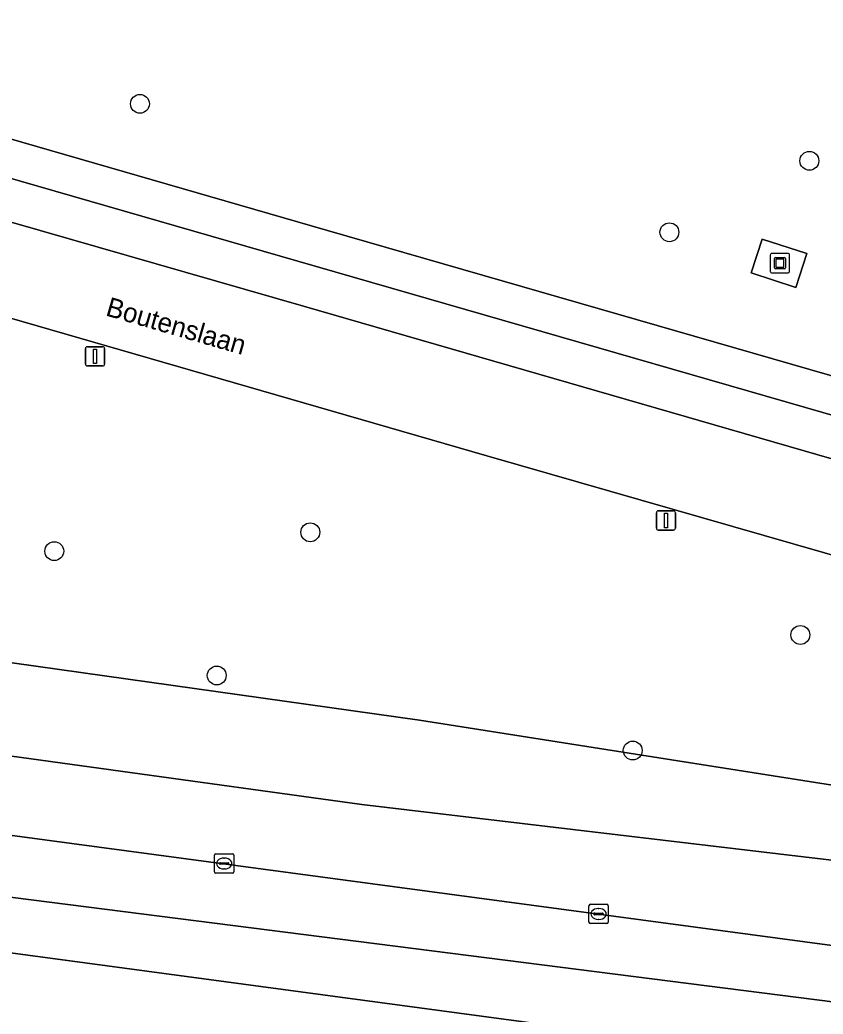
# Model space of a CAD drawing. Extents: x 161402 to 161933, y 381647 to 382315.
# Drawn here: x 161443.8 to 161485.4, y 381705.2 to 381756.7 of the extents above; entities that cross this region are included whole.
import ezdxf

# ---------------------------------------------------------------- set-up
doc = ezdxf.new("R2010")
doc.units = 0
for name, color, linetype in [('IMGEO_Berm_groen', 7, 'Continuous'), ('IMGEO_Boom', 7, 'Continuous'), ('IMGEO_Groenvoorziening', 7, 'Continuous'), ('IMGEO_Kolk', 7, 'Continuous'), ('IMGEO_Kunstobject', 7, 'Continuous'), ('IMGEO_Lichtmast', 7, 'Continuous'), ('IMGEO_Openbare_ruimte_label', 7, 'Continuous'), ('IMGEO_Parkeervlak_halfverhard', 7, 'Continuous'), ('IMGEO_Rijbaan_lokaal_open', 7, 'Continuous'), ('IMGEO_Rijbaan_regionaal_gesloten', 7, 'Continuous'), ('IMGEO_Voetpad_open', 7, 'Continuous')]:
    doc.layers.add(name, color=color, linetype=linetype)

msp = doc.modelspace()

# ---------------------------------------------------------------- linework, layer by layer
at = {"layer": 'IMGEO_Berm_groen'}
for points in [[(161550.274, 381710.457), (161521.825, 381718.639), (161511.545, 381721.598), (161506.198, 381723.137), (161493.45, 381726.806), (161492.294, 381723.245), (161489.647, 381724.03), (161487.722, 381724.601), (161488.157, 381726.039), (161486.53, 381726.524), (161487.109, 381728.631), (161467.984, 381734.136), (161424.232, 381746.77), (161422.307, 381747.284), (161421.908, 381747.401), (161419.883, 381747.931), (161419.264, 381745.56), (161418.377, 381745.755)], [(161412.782, 381706.187), (161412.983, 381707.708), (161413.616, 381712.377), (161413.962, 381714.993), (161414.406, 381718.345), (161414.713, 381720.679), (161414.729, 381720.986), (161414.872, 381722.243), (161415.659, 381723.737), (161416.807, 381724.974), (161417.694, 381725.496), (161419.991, 381725.975), (161422.336, 381726.035), (161425.949, 381725.851), (161464.494, 381720.439), (161486.232, 381717.019)], [(161486.232, 381717.019), (161464.494, 381720.439), (161425.949, 381725.851), (161422.336, 381726.035), (161419.991, 381725.975), (161417.694, 381725.496), (161416.807, 381724.974), (161415.659, 381723.737), (161414.872, 381722.243), (161414.729, 381720.986), (161421.115, 381720.1), (161421.193, 381720.541), (161421.637, 381721.268), (161422.47, 381721.45), (161461.503, 381716.064), (161500, 381711.507)], [(161619.348, 381684.737), (161582.68, 381689.648), (161413.616, 381712.377), (161412.983, 381707.708), (161436.501, 381704.561), (161496.223, 381696.587), (161500, 381696.081), (161535.035, 381691.391), (161618.812, 381680.164), (161638.545, 381677.519), (161680.265, 381671.952)]]:
    msp.add_lwpolyline(points, dxfattribs=at)
msp.add_lwpolyline([(161506.756, 381710.29), (161500, 381711.507), (161461.503, 381716.064), (161422.47, 381721.45), (161421.637, 381721.268), (161421.193, 381720.541), (161421.115, 381720.1), (161414.729, 381720.986), (161414.713, 381720.679), (161414.406, 381718.345), (161620.052, 381690.763), (161588.605, 381697.419), (161577.445, 381699.644), (161568.717, 381701.384), (161533, 381706.394)], close=True, dxfattribs=at)
at = {"layer": 'IMGEO_Boom'}
for centre in [(161450.011, 381752.364), (161484.7, 381749.414), (161477.448, 381745.711), (161458.839, 381730.166), (161445.572, 381729.191), (161484.233, 381724.847), (161453.99, 381722.748), (161475.546, 381718.86)]:
    msp.add_circle(centre, 0.489, dxfattribs=at)
at = {"layer": 'IMGEO_Groenvoorziening'}
msp.add_lwpolyline([(161421.928, 381756.713), (161459.737, 381745.805), (161494.788, 381735.694), (161509.376, 381731.463), (161508.478, 381735.358), (161508.026, 381737.392), (161507.691, 381738.967), (161506.96, 381742.59), (161506.607, 381744.402), (161506.258, 381746.213), (161505.559, 381749.824), (161505.195, 381751.629), (161504.692, 381753.976)], dxfattribs=at)
msp.add_lwpolyline([(161484.569, 381744.613), (161484.001, 381742.857), (161481.687, 381743.605), (161482.255, 381745.361)], close=True, dxfattribs=at)
at = {"layer": 'IMGEO_Kolk'}
for p, q in [((161453.875, 381712.582), (161453.875, 381713.434)), ((161453.95, 381713.508), (161454.802, 381713.508)), ((161454.363, 381713.288), (161454.388, 381713.288)), ((161454.876, 381713.434), (161454.876, 381712.582)), ((161454.134, 381713.002), (161454.134, 381713.014)), ((161454.572, 381712.965), (161454.174, 381712.965)), ((161454.177, 381713.051), (161454.575, 381713.051)), ((161454.386, 381712.728), (161454.361, 381712.728)), ((161454.618, 381713.014), (161454.618, 381713.002)), ((161454.802, 381712.508), (161453.95, 381712.508)), ((161473.276, 381709.967), (161473.276, 381710.819)), ((161473.351, 381710.893), (161474.203, 381710.893)), ((161473.764, 381710.673), (161473.789, 381710.673)), ((161474.277, 381710.819), (161474.277, 381709.967)), ((161473.535, 381710.387), (161473.535, 381710.399)), ((161473.973, 381710.35), (161473.575, 381710.35)), ((161473.578, 381710.436), (161473.976, 381710.436)), ((161473.787, 381710.113), (161473.762, 381710.113)), ((161474.019, 381710.399), (161474.019, 381710.387)), ((161474.203, 381709.893), (161473.351, 381709.893))]:
    msp.add_line(p, q, dxfattribs=at)
for points in [[(161453.875, 381712.582), (161453.875, 381713.434)], [(161453.95, 381713.508), (161454.802, 381713.508)], [(161454.876, 381713.434), (161454.876, 381712.582)], [(161454.802, 381712.508), (161453.95, 381712.508)], [(161473.276, 381709.967), (161473.276, 381710.819)], [(161473.351, 381710.893), (161474.203, 381710.893)], [(161474.277, 381710.819), (161474.277, 381709.967)], [(161474.203, 381709.893), (161473.351, 381709.893)]]:
    msp.add_lwpolyline(points, dxfattribs=at)
for centre, radius, start, end in [((161453.952, 381713.432), 0.0765, 91.552, 178.448), ((161453.952, 381713.432), 0.0765, 91.552, 178.448), ((161454.8, 381713.432), 0.0765, 1.552, 88.448), ((161454.8, 381713.432), 0.0765, 1.552, 88.448), ((161453.952, 381712.584), 0.0765, 181.552, 268.448), ((161453.952, 381712.584), 0.0765, 181.552, 268.448), ((161454.174, 381713.011), 0.0403, 85.8775, 175.7526), ((161454.171, 381713.001), 0.0366, 178.938, 274.7102), ((161454.575, 381713.008), 0.043, 264.8664, 352.4533), ((161454.579, 381713.013), 0.0386, 1.7309, 96.639), ((161454.8, 381712.584), 0.0765, 271.552, 358.448), ((161454.8, 381712.584), 0.0765, 271.552, 358.448), ((161473.353, 381710.817), 0.0765, 91.552, 178.448), ((161473.353, 381710.817), 0.0765, 91.552, 178.448), ((161474.201, 381710.817), 0.0765, 1.552, 88.448), ((161474.201, 381710.817), 0.0765, 1.552, 88.448), ((161473.575, 381710.396), 0.0403, 85.8775, 175.7526), ((161473.572, 381710.386), 0.0366, 178.938, 274.7102), ((161473.976, 381710.393), 0.043, 264.8664, 352.4533), ((161473.98, 381710.398), 0.0386, 1.7309, 96.639), ((161473.353, 381709.969), 0.0765, 181.552, 268.448), ((161473.353, 381709.969), 0.0765, 181.552, 268.448), ((161474.201, 381709.969), 0.0765, 271.552, 358.448), ((161474.201, 381709.969), 0.0765, 271.552, 358.448)]:
    msp.add_arc(centre, radius, start, end, dxfattribs=at)
for centre, major_axis, ratio, start_param, end_param in [((161454.362, 381713.008), (-0.387, 0.002), 0.722429, 4.712389, 7.853982), ((161454.387, 381713.008), (-0.39, 0.002), 0.717154, 1.570796, 4.712389), ((161473.763, 381710.393), (-0.387, 0.002), 0.722429, 4.712389, 7.853982), ((161473.788, 381710.393), (-0.39, 0.002), 0.717154, 1.570796, 4.712389)]:
    msp.add_ellipse(centre, major_axis=major_axis, ratio=ratio, start_param=start_param, end_param=end_param, dxfattribs=at)
at = {"layer": 'IMGEO_Kunstobject'}
for p, q in [((161482.677, 381744.526), (161482.677, 381743.685)), ((161482.677, 381744.526), (161482.677, 381743.685)), ((161483.593, 381744.61), (161482.752, 381744.61)), ((161483.593, 381744.61), (161482.752, 381744.61)), ((161483.677, 381743.694), (161483.677, 381744.535)), ((161483.677, 381743.694), (161483.677, 381744.535)), ((161482.891, 381743.874), (161482.891, 381744.348)), ((161482.941, 381744.398), (161483.415, 381744.398)), ((161482.971, 381744.298), (161482.971, 381743.924)), ((161483.365, 381744.318), (161482.991, 381744.318)), ((161483.385, 381743.924), (161483.385, 381744.298)), ((161483.465, 381744.348), (161483.465, 381743.874)), ((161482.761, 381743.61), (161483.602, 381743.61)), ((161482.761, 381743.61), (161483.602, 381743.61)), ((161483.415, 381743.824), (161482.941, 381743.824)), ((161482.991, 381743.904), (161483.365, 381743.904))]:
    msp.add_line(p, q, dxfattribs=at)
for centre, radius, start, end in [((161482.755, 381744.532), 0.0779, 92.4484, 184.2845), ((161482.755, 381744.532), 0.0779, 92.4484, 184.2845), ((161483.599, 381744.532), 0.0779, 2.4484, 94.2845), ((161483.599, 381744.532), 0.0779, 2.4484, 94.2845), ((161482.941, 381744.348), 0.05, 90, 180), ((161482.991, 381744.298), 0.02, 90, 180), ((161483.365, 381744.298), 0.02, 360, 90), ((161483.415, 381744.348), 0.05, 360, 90), ((161482.755, 381743.688), 0.0779, 182.4484, 274.2845), ((161482.755, 381743.688), 0.0779, 182.4484, 274.2845), ((161482.941, 381743.874), 0.05, 180, 270), ((161482.991, 381743.924), 0.02, 180, 270), ((161483.365, 381743.924), 0.02, 270, 0), ((161483.415, 381743.874), 0.05, 270, 0), ((161483.599, 381743.688), 0.0779, 272.4484, 4.2845), ((161483.599, 381743.688), 0.0779, 272.4484, 4.2845)]:
    msp.add_arc(centre, radius, start, end, dxfattribs=at)
at = {"layer": 'IMGEO_Lichtmast'}
for p, q in [((161447.187, 381738.883), (161447.187, 381739.683)), ((161447.187, 381739.683), (161447.187, 381738.883)), ((161447.287, 381739.783), (161448.077, 381739.783)), ((161448.077, 381739.783), (161447.287, 381739.783)), ((161448.177, 381739.683), (161448.177, 381738.883)), ((161448.177, 381738.883), (161448.177, 381739.683)), ((161448.077, 381738.783), (161447.287, 381738.783)), ((161447.287, 381738.783), (161448.077, 381738.783)), ((161476.77, 381730.378), (161476.77, 381731.178)), ((161476.77, 381731.178), (161476.77, 381730.378)), ((161476.87, 381731.278), (161477.66, 381731.278)), ((161477.66, 381731.278), (161476.87, 381731.278)), ((161477.76, 381731.178), (161477.76, 381730.378)), ((161477.76, 381730.378), (161477.76, 381731.178)), ((161477.66, 381730.278), (161476.87, 381730.278)), ((161476.87, 381730.278), (161477.66, 381730.278))]:
    msp.add_line(p, q, dxfattribs=at)
for points in [[(161447.607, 381739.658), (161447.757, 381739.658), (161447.757, 381738.908), (161447.607, 381738.908), (161447.607, 381739.658)], [(161477.19, 381731.153), (161477.34, 381731.153), (161477.34, 381730.403), (161477.19, 381730.403), (161477.19, 381731.153)]]:
    msp.add_lwpolyline(points, dxfattribs=at)
for centre, start, end in [((161447.287, 381739.683), 90, 180), ((161447.287, 381739.683), 90, 180), ((161448.077, 381739.683), 0, 90), ((161448.077, 381739.683), 360, 90), ((161447.287, 381738.883), 180, 270), ((161447.287, 381738.883), 180, 270), ((161448.077, 381738.883), 270, 0), ((161448.077, 381738.883), 270, 0), ((161476.87, 381731.178), 90, 180), ((161476.87, 381731.178), 90, 180), ((161477.66, 381731.178), 0, 90), ((161477.66, 381731.178), 360, 90), ((161476.87, 381730.378), 180, 270), ((161476.87, 381730.378), 180, 270), ((161477.66, 381730.378), 270, 0), ((161477.66, 381730.378), 270, 0)]:
    msp.add_arc(centre, 0.1, start, end, dxfattribs=at)
at = {"layer": 'IMGEO_Parkeervlak_halfverhard'}
msp.add_lwpolyline([(161423.537, 381751.922), (161458.483, 381741.876), (161493.525, 381731.759), (161507.502, 381727.744), (161512.889, 381726.196), (161550.839, 381715.295), (161551.402, 381717.349), (161494.2, 381733.836), (161459.096, 381743.949), (161424.159, 381754.017)], close=True, dxfattribs=at)
at = {"layer": 'IMGEO_Rijbaan_lokaal_open'}
msp.add_lwpolyline([(161458.483, 381741.876), (161423.537, 381751.922), (161423.15, 381752.027), (161421.908, 381747.401), (161422.307, 381747.284), (161424.232, 381746.77), (161467.984, 381734.136), (161487.109, 381728.631), (161490.705, 381727.596), (161493.45, 381726.806), (161506.198, 381723.137), (161507.502, 381727.744), (161493.525, 381731.759)], close=True, dxfattribs=at)
at = {"layer": 'IMGEO_Rijbaan_regionaal_gesloten'}
for points in [[(161620.052, 381690.763), (161414.406, 381718.345), (161413.962, 381714.993), (161500.28, 381704.009), (161533.162, 381699.103), (161549.132, 381696.713), (161592.199, 381691.43), (161619.672, 381687.503), (161753.907, 381669.29), (161804.206, 381663.251), (161819.974, 381662.23), (161820.308, 381665.138), (161820.232, 381665.145), (161818.101, 381665.382), (161799.835, 381667.417), (161794.737, 381667.864), (161786.397, 381668.675), (161776.791, 381669.741)], [(161413.962, 381714.993), (161413.616, 381712.377), (161582.68, 381689.648), (161619.348, 381684.737), (161785.447, 381662.49), (161799.427, 381660.835), (161819.493, 381658.805), (161819.974, 381662.23), (161804.206, 381663.251), (161753.907, 381669.29), (161619.672, 381687.503), (161592.199, 381691.43), (161549.132, 381696.713), (161533.162, 381699.103), (161500.28, 381704.009)]]:
    msp.add_lwpolyline(points, close=True, dxfattribs=at)
at = {"layer": 'IMGEO_Voetpad_open'}
for points in [[(161553.492, 381718.791), (161537.607, 381723.359), (161538.069, 381724.94), (161534.993, 381725.82), (161534.541, 381724.258), (161512.992, 381730.464), (161512.982, 381730.467), (161509.404, 381731.455), (161509.376, 381731.463), (161494.788, 381735.694), (161459.737, 381745.805), (161421.928, 381756.713)], [(161417.345, 381753.691), (161423.15, 381752.027), (161423.537, 381751.922), (161424.159, 381754.017), (161459.096, 381743.949), (161494.2, 381733.836), (161551.402, 381717.349), (161550.839, 381715.295), (161552.041, 381715.004)]]:
    msp.add_lwpolyline(points, dxfattribs=at)
msp.add_lwpolyline([(161484.569, 381744.613), (161482.255, 381745.361), (161481.687, 381743.605), (161484.001, 381742.857)], close=True, dxfattribs=at)

# ---------------------------------------------------------------- texts
at = {"layer": 'IMGEO_Openbare_ruimte_label'}
msp.add_text('Boutenslaan', height=1, rotation=343.9208, dxfattribs=at).set_placement((161448.184, 381741.409))

doc.saveas('drawing.dxf')
